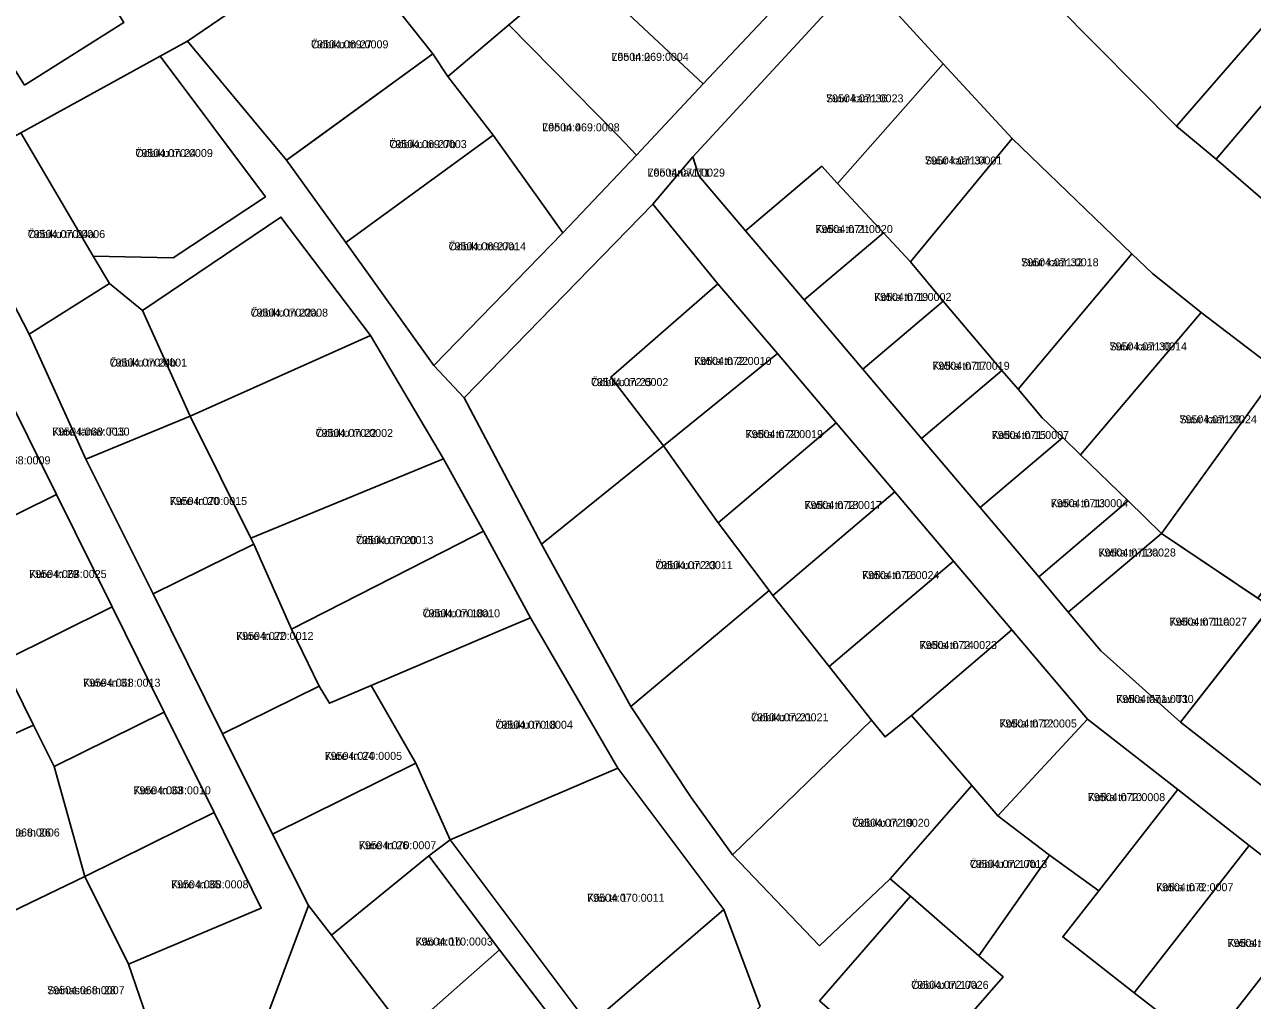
# Model space of a CAD drawing. Extents: x 643847 to 663718, y 6468443 to 6482775.
# Drawn here: x 658246.9 to 658477, y 6471809.8 to 6471992.7 of the extents above; entities that cross this region are included whole.
import ezdxf

# ---------------------------------------------------------------- set-up
doc = ezdxf.new("R2010")
doc.units = 0
for name, color, linetype in [('L_AADRESS', 7, 'Continuous'), ('PIIR', 7, 'Continuous'), ('TUNNUS', 7, 'Continuous')]:
    doc.layers.add(name, color=color, linetype=linetype)

msp = doc.modelspace()

# ---------------------------------------------------------------- linework, layer by layer
at = {"layer": 'PIIR'}
for points in [[(658486.97, 6471987.22), (658470.14, 6471967.41), (658462.76, 6471973.64), (658481.78, 6471995.53), (658502.37, 6472019.24), (658520.73, 6472040.77), (658544.18, 6472069.39), (658548.25, 6472074.35), (658574.77, 6472108.01), (658585.28, 6472121.63), (658597.38, 6472137.31), (658620.68, 6472168.8), (658629.38, 6472163.16), (658609.28, 6472136.89), (658597.33, 6472121.3), (658586.04, 6472105.83), (658580.96, 6472099.65), (658555.3, 6472067.81), (658551.14, 6472062.72), (658529, 6472036.46), (658513.76, 6472018.4), (658509.71, 6472013.53)], [(658379.22, 6472034.21), (658398.69, 6472007.8), (658374.03, 6471981.52), (658370.39, 6471984.94), (658350.57, 6472003.51), (658363.17, 6472017.02)], [(658440.06, 6471996.47), (658454.33, 6472012.08), (658459.63, 6472017.87), (658481.78, 6471995.53), (658462.76, 6471973.64)], [(658246.85, 6471981.3), (658232.47, 6472004.15), (658251.08, 6472015.88), (658265.46, 6471993.03)], [(658320.86, 6472000.73), (658340.33, 6472012.98), (658350.57, 6472003.51), (658337.64, 6471992.59), (658326.2, 6471982.92), (658323.4, 6471987.19), (658315.36, 6471997.27)], [(658277.4, 6471989.53), (658306.11, 6472009.17), (658315.36, 6471997.27), (658323.4, 6471987.19), (658299.95, 6471970.14), (658295.95, 6471967.23)], [(658403.66, 6472002.11), (658372.1, 6471967.86), (658364.62, 6471958.97), (658329.23, 6471922.68), (658323.57, 6471928.79), (658347.76, 6471953.61), (658361.56, 6471968.19), (658374.03, 6471981.52), (658398.69, 6472007.8)], [(658374.03, 6471981.52), (658361.56, 6471968.19), (658358.08, 6471971.8), (658337.64, 6471992.59), (658350.57, 6472003.51), (658370.39, 6471984.94)], [(658419.02, 6471985.3), (658399.22, 6471962.89), (658396.25, 6471966.11), (658381.99, 6471954.02), (658373.24, 6471964.3), (658372.1, 6471967.86), (658403.66, 6472002.11)], [(658347.76, 6471953.61), (658344.86, 6471957.67), (658334.69, 6471971.91), (658326.2, 6471982.92), (658337.64, 6471992.59), (658358.08, 6471971.8), (658361.56, 6471968.19)], [(658292.01, 6471960.35), (658274.73, 6471948.93), (658259.73, 6471949.27), (658246.18, 6471972.39), (658272.3, 6471986.72)], [(658323.4, 6471987.19), (658326.2, 6471982.92), (658334.69, 6471971.91), (658307.04, 6471951.8), (658295.95, 6471967.23)], [(658431.94, 6471971.31), (658412.91, 6471948.21), (658407.83, 6471953.64), (658399.22, 6471962.89), (658419.02, 6471985.3)], [(658470.14, 6471967.41), (658486.97, 6471987.22), (658503.61, 6471972.83), (658486.78, 6471953.07)], [(658259.73, 6471949.27), (658262.77, 6471944.1), (658247.71, 6471934.61), (658232.16, 6471964.7), (658246.18, 6471972.39)], [(658323.57, 6471928.79), (658307.04, 6471951.8), (658334.69, 6471971.91), (658344.86, 6471957.67), (658347.76, 6471953.61)], [(658454.35, 6471949.67), (658433.04, 6471924.32), (658429.98, 6471927.84), (658419.01, 6471940.82), (658412.91, 6471948.21), (658431.94, 6471971.31)], [(658381.99, 6471954.02), (658396.25, 6471966.11), (658399.22, 6471962.89), (658407.83, 6471953.64), (658392.98, 6471941.05)], [(658329.23, 6471922.68), (658364.62, 6471958.97), (658376.79, 6471944.06), (658356.73, 6471926.6), (658366.57, 6471913.68), (658343.75, 6471895.26)], [(658277.91, 6471919.28), (658268.94, 6471939.05), (658294.89, 6471956.56), (658311.71, 6471934.36)], [(658392.98, 6471941.05), (658407.83, 6471953.64), (658412.91, 6471948.21), (658419.01, 6471940.82), (658403.97, 6471928.08)], [(658458.25, 6471946), (658467.34, 6471938.7), (658444.74, 6471912.02), (658441.42, 6471915.25), (658437.57, 6471918.98), (658433.04, 6471924.32), (658454.35, 6471949.67)], [(658268.94, 6471939.05), (658277.91, 6471919.28), (658258.33, 6471911.21), (658247.71, 6471934.61), (658262.77, 6471944.1)], [(658387.97, 6471931.02), (658366.57, 6471913.68), (658356.73, 6471926.6), (658376.79, 6471944.06)], [(658403.97, 6471928.08), (658419.01, 6471940.82), (658429.98, 6471927.84), (658414.96, 6471915.11)], [(658467.34, 6471938.7), (658481.84, 6471927.64), (658459.94, 6471897.31), (658453.67, 6471903.38), (658444.74, 6471912.02)], [(658325.4, 6471911.26), (658289.25, 6471896.38), (658277.91, 6471919.28), (658311.71, 6471934.36)], [(658398.96, 6471918.05), (658376.84, 6471899.31), (658366.57, 6471913.68), (658387.97, 6471931.02)], [(658414.96, 6471915.11), (658429.98, 6471927.84), (658433.04, 6471924.32), (658437.57, 6471918.98), (658441.42, 6471915.25), (658425.95, 6471902.14)], [(658252.84, 6471904.59), (658232.22, 6471894.39), (658221.58, 6471915.89), (658226.96, 6471918.56), (658242.19, 6471926.09)], [(658499.39, 6471913.75), (658477.99, 6471885.14), (658459.94, 6471897.31), (658481.84, 6471927.64)], [(658258.33, 6471911.21), (658277.91, 6471919.28), (658289.25, 6471896.38), (658289.8, 6471895.3), (658270.95, 6471886)], [(658409.95, 6471905.08), (658387.07, 6471885.69), (658386.4, 6471886.58), (658376.84, 6471899.31), (658398.96, 6471918.05)], [(658436.94, 6471889.16), (658425.95, 6471902.14), (658441.42, 6471915.25), (658444.74, 6471912.02), (658453.67, 6471903.38)], [(658343.75, 6471895.26), (658366.57, 6471913.68), (658376.84, 6471899.31), (658386.4, 6471886.58), (658360.45, 6471864.86)], [(658332.85, 6471897.7), (658328.4, 6471895.42), (658296.91, 6471879.33), (658289.8, 6471895.3), (658289.25, 6471896.38), (658325.4, 6471911.26)], [(658420.94, 6471892.11), (658397.67, 6471872.39), (658387.07, 6471885.69), (658409.95, 6471905.08)], [(658263.26, 6471883.52), (658242.64, 6471873.32), (658235.36, 6471888.05), (658232.22, 6471894.39), (658252.84, 6471904.59)], [(658453.67, 6471903.38), (658459.94, 6471897.31), (658442.45, 6471882.56), (658436.94, 6471889.16)], [(658341.66, 6471881.49), (658337.07, 6471879.53), (658311.82, 6471868.79), (658304, 6471865.46), (658302.06, 6471868.7), (658296.91, 6471879.33), (658328.4, 6471895.42), (658332.85, 6471897.7)], [(658459.94, 6471897.31), (658478.02, 6471885.13), (658480.41, 6471883.57), (658463.45, 6471861.9), (658448.57, 6471875.27), (658442.45, 6471882.56)], [(658270.95, 6471886), (658289.8, 6471895.3), (658296.91, 6471879.33), (658302.06, 6471868.7), (658283.95, 6471859.74)], [(658431.89, 6471879.2), (658413.06, 6471863.18), (658408.11, 6471859.15), (658405.57, 6471862.28), (658397.67, 6471872.39), (658420.94, 6471892.11)], [(658207.37, 6471876.32), (658235.36, 6471888.05), (658242.64, 6471873.32), (658248.56, 6471861.38), (658218.77, 6471847.97)], [(658371.8, 6471847.82), (658360.45, 6471864.86), (658386.4, 6471886.58), (658387.07, 6471885.69), (658397.67, 6471872.39), (658405.57, 6471862.28), (658379.54, 6471837.07)], [(658273.02, 6471863.81), (658252.4, 6471853.61), (658248.56, 6471861.38), (658242.64, 6471873.32), (658263.26, 6471883.52)], [(658463.48, 6471861.9), (658480.38, 6471883.58), (658485.41, 6471880.31), (658487.09, 6471879.01), (658498.83, 6471869.87), (658481.63, 6471847.77)], [(658358.03, 6471853.3), (658326.65, 6471839.89), (658320.19, 6471854.22), (658311.82, 6471868.79), (658337.07, 6471879.53), (658341.66, 6471881.49)], [(658446.03, 6471862.48), (658429.27, 6471844.35), (658424.4, 6471850.05), (658413.06, 6471863.18), (658431.89, 6471879.2)], [(658283.95, 6471859.74), (658302.06, 6471868.7), (658304, 6471865.46), (658311.82, 6471868.79), (658320.19, 6471854.22), (658293.3, 6471840.92)], [(658282.37, 6471844.99), (658258.17, 6471833.02), (658252.4, 6471853.61), (658273.02, 6471863.81)], [(658218.77, 6471847.97), (658248.56, 6471861.38), (658252.4, 6471853.61), (658258.17, 6471833.02), (658230.36, 6471819.62)], [(658379.54, 6471837.07), (658405.57, 6471862.28), (658408.11, 6471859.15), (658413.06, 6471863.18), (658424.4, 6471850.05), (658409.1, 6471832.6), (658395.84, 6471820.03)], [(658462.95, 6471849.28), (658448.19, 6471830.35), (658438.92, 6471837), (658429.27, 6471844.35), (658446.03, 6471862.48)], [(658300.1, 6471827.59), (658293.3, 6471840.92), (658320.19, 6471854.22), (658326.65, 6471839.89), (658322.65, 6471836.89), (658304.36, 6471822.02)], [(658377.92, 6471826.8), (658352.67, 6471805.18), (658326.65, 6471839.89), (658358.03, 6471853.3)], [(658412.87, 6471829.31), (658409.1, 6471832.6), (658424.4, 6471850.05), (658429.27, 6471844.35), (658438.92, 6471837), (658425.69, 6471818.15)], [(658448.19, 6471830.35), (658462.95, 6471849.28), (658476.35, 6471838.83), (658454.82, 6471811.23), (658441.42, 6471821.68)], [(658291.23, 6471827.07), (658266.34, 6471816.6), (658258.17, 6471833.02), (658282.37, 6471844.99)], [(658377.92, 6471826.8), (658384.7, 6471808.64), (658370.37, 6471794.57), (658361.95, 6471786.11), (658359.27, 6471789.16), (658355, 6471785.23), (658330.45, 6471762.66), (658323.31, 6471756.93), (658307.14, 6471745.74), (658273.59, 6471720.09), (658264.99, 6471735.67), (658270.23, 6471731.61), (658281.89, 6471735.34), (658300.85, 6471749.01), (658316.72, 6471761.21), (658320.94, 6471764.7), (658337.26, 6471778.98), (658354.27, 6471795.15), (658335.85, 6471819.29), (658322.65, 6471836.89), (658326.65, 6471839.89), (658352.67, 6471805.18)], [(658489.75, 6471828.38), (658468.22, 6471800.78), (658467.51, 6471801.33), (658454.82, 6471811.23), (658476.35, 6471838.83)], [(658335.85, 6471819.29), (658318.33, 6471803.75), (658304.36, 6471822.02), (658322.65, 6471836.89)], [(658413.16, 6471794.6), (658430.22, 6471814.21), (658425.69, 6471818.15), (658438.92, 6471837), (658448.19, 6471830.35), (658441.42, 6471821.68), (658454.82, 6471811.23), (658467.51, 6471801.33), (658441.97, 6471768.76)], [(658230.36, 6471819.62), (658258.17, 6471833.02), (658266.34, 6471816.6), (658271.85, 6471800.57), (658242.75, 6471788.94)], [(658395.81, 6471809.7), (658412.87, 6471829.31), (658425.69, 6471818.15), (658430.22, 6471814.21), (658413.16, 6471794.6)], [(658320.94, 6471764.7), (658290.4, 6471801.72), (658300.1, 6471827.59), (658304.36, 6471822.02), (658318.33, 6471803.75), (658337.26, 6471778.98)], [(658503.15, 6471817.93), (658481.62, 6471790.33), (658468.22, 6471800.78), (658489.75, 6471828.38)], [(658337.26, 6471778.98), (658318.33, 6471803.75), (658335.85, 6471819.29), (658354.27, 6471795.15)]]:
    msp.add_lwpolyline(points, close=True, dxfattribs=at)
for points in [[(658481.84, 6471927.64), (658467.34, 6471938.7), (658458.25, 6471946), (658454.35, 6471949.67), (658431.94, 6471971.31), (658419.02, 6471985.3), (658403.66, 6472002.11), (658398.69, 6472007.8), (658418.28, 6472021.46), (658423.46, 6472015.52), (658440.06, 6471996.47), (658462.76, 6471973.64), (658470.14, 6471967.41), (658486.78, 6471953.07)], [(658306.11, 6472009.17), (658277.4, 6471989.53), (658272.3, 6471986.72), (658246.18, 6471972.39)], [(658246.85, 6471981.3), (658265.46, 6471993.03)], [(658384.7, 6471808.64), (658377.92, 6471826.8), (658358.03, 6471853.3), (658341.66, 6471881.49), (658332.85, 6471897.7), (658325.4, 6471911.26), (658311.71, 6471934.36), (658294.89, 6471956.56), (658268.94, 6471939.05), (658262.77, 6471944.1), (658259.73, 6471949.27), (658274.73, 6471948.93), (658292.01, 6471960.35), (658272.3, 6471986.72), (658277.4, 6471989.53), (658295.95, 6471967.23), (658307.04, 6471951.8), (658323.57, 6471928.79), (658329.23, 6471922.68), (658343.75, 6471895.26), (658360.45, 6471864.86), (658371.8, 6471847.82), (658379.54, 6471837.07), (658395.84, 6471820.03), (658409.1, 6471832.6), (658412.87, 6471829.31), (658395.81, 6471809.7)], [(658489.75, 6471828.38), (658476.35, 6471838.83), (658462.95, 6471849.28), (658446.03, 6471862.48), (658431.89, 6471879.2), (658420.94, 6471892.11), (658409.95, 6471905.08), (658398.96, 6471918.05), (658387.97, 6471931.02), (658376.79, 6471944.06), (658364.62, 6471958.97), (658372.1, 6471967.86), (658373.24, 6471964.3), (658381.99, 6471954.02), (658392.98, 6471941.05), (658403.97, 6471928.08), (658414.96, 6471915.11), (658425.95, 6471902.14), (658436.94, 6471889.16), (658442.45, 6471882.56), (658448.57, 6471875.27), (658463.45, 6471861.9), (658481.63, 6471847.77)], [(658232.16, 6471964.7), (658247.71, 6471934.61), (658258.33, 6471911.21), (658270.95, 6471886), (658283.95, 6471859.74), (658293.3, 6471840.92), (658300.1, 6471827.59), (658290.4, 6471801.72), (658320.94, 6471764.7), (658316.72, 6471761.21), (658296.98, 6471785.11), (658291.89, 6471780.91), (658276.11, 6471802.62), (658271.85, 6471800.57), (658266.34, 6471816.6), (658291.23, 6471827.07), (658282.37, 6471844.99), (658273.02, 6471863.81), (658263.26, 6471883.52), (658252.84, 6471904.59), (658242.19, 6471926.09)]]:
    msp.add_lwpolyline(points, dxfattribs=at)

# ---------------------------------------------------------------- texts
at = {"layer": 'L_AADRESS'}
for s, p in [('Ööbiku tn 27', (658300.55, 6471988.2)), ('Lõo tn 2', (658356.84, 6471985.85)), ('Suur kaar 36', (658397.07, 6471978.07)), ('Lõo tn 4', (658343.88, 6471972.64)), ('Ööbiku tn 24', (658267.64, 6471967.82)), ('Ööbiku tn 27b', (658315.22, 6471969.5)), ('Suur kaar 34', (658415.58, 6471966.43)), ('Lõo tänav T1', (658363.61, 6471964.16)), ('Ööbiku tn 24a', (658247.46, 6471952.64)), ('Kotka tn 21', (658395.06, 6471953.58)), ('Ööbiku tn 27a', (658326.33, 6471950.35)), ('Suur kaar 32', (658433.63, 6471947.35)), ('Kotka tn 19', (658406.06, 6471940.86)), ('Ööbiku tn 22a', (658289.23, 6471937.92)), ('Suur kaar 30', (658450.19, 6471931.59)), ('Ööbiku tn 24b', (658262.81, 6471928.56)), ('Kotka tn 22', (658372.33, 6471928.87)), ('Kotka tn 17', (658416.97, 6471927.96)), ('Ööbiku tn 25', (658353.01, 6471924.9)), ('Suur kaar 28', (658463.29, 6471917.93)), ('Kure tänav T15', (658252.04, 6471915.63)), ('Ööbiku tn 22', (658301.41, 6471915.37)), ('Kotka tn 20', (658381.98, 6471915.16)), ('Kotka tn 15', (658428.09, 6471914.99)), ('Kure tn 20', (658274.06, 6471902.62)), ('Kotka tn 18', (658393.01, 6471901.87)), ('Kotka tn 13', (658439.16, 6471902.21)), ('Ööbiku tn 20', (658308.98, 6471895.29)), ('Kotka tn 13a', (658448.11, 6471892.97)), ('Ööbiku tn 23', (658365.07, 6471890.6)), ('Kure tn 29', (658247.74, 6471888.95)), ('Kotka tn 16', (658403.81, 6471888.74)), ('Ööbiku tn 18a', (658321.46, 6471881.58)), ('Kotka tn 11a', (658461.43, 6471880.01)), ('Kure tn 22', (658286.51, 6471877.34)), ('Kotka tn 14', (658414.59, 6471875.63)), ('Kure tn 31', (658257.83, 6471868.57)), ('Kotka tänav T1', (658451.44, 6471865.52)), ('Ööbiku tn 21', (658383.01, 6471862.09)), ('Ööbiku tn 18', (658335.11, 6471860.69)), ('Kotka tn 12', (658429.55, 6471860.93)), ('Kure tn 24', (658303.1, 6471854.86)), ('Kure tn 33', (658267.26, 6471848.41)), ('Kotka tn 10', (658446.11, 6471847.13)), ('Ööbiku tn 19', (658401.97, 6471842.32)), ('Soinaste tn 26', (658238.95, 6471840.5)), ('Kure tn 26', (658309.51, 6471838.12)), ('Ööbiku tn 17b', (658424.01, 6471834.61)), ('Kure tn 35', (658274.33, 6471830.79)), ('Kotka tn 8', (658458.89, 6471830.25)), ('Käo tn 1', (658352.29, 6471828.27)), ('Käo tn 1b', (658320.11, 6471820.07)), ('Kotka tn 6', (658472.29, 6471819.8)), ('Ööbiku tn 17a', (658413.02, 6471811.95)), ('Soinaste tn 28', (658251.11, 6471810.95))]:
    msp.add_text(s, height=1.5, dxfattribs=at).set_placement(p)
at = {"layer": 'TUNNUS'}
for s, p in [('79504:069:0009', (658300.55, 6471988.2)), ('79504:069:0004', (658356.84, 6471985.85)), ('79504:071:0023', (658397.07, 6471978.07)), ('79504:069:0008', (658343.88, 6471972.64)), ('79504:070:0009', (658267.64, 6471967.82)), ('79504:069:0003', (658315.22, 6471969.5)), ('79504:071:0001', (658415.58, 6471966.43)), ('79504:071:0029', (658363.61, 6471964.16)), ('79504:070:0006', (658247.46, 6471952.64)), ('79504:071:0020', (658395.06, 6471953.58)), ('79504:069:0014', (658326.33, 6471950.35)), ('79504:071:0018', (658433.63, 6471947.35)), ('79504:071:0002', (658406.06, 6471940.86)), ('79504:070:0008', (658289.23, 6471937.92)), ('79504:071:0014', (658450.19, 6471931.59)), ('79504:070:0001', (658262.81, 6471928.56)), ('79504:072:0010', (658372.33, 6471928.87)), ('79504:071:0019', (658416.97, 6471927.96)), ('79504:072:0002', (658353.01, 6471924.9)), ('79504:071:0024', (658463.29, 6471917.93)), ('79504:068:0030', (658252.04, 6471915.63)), ('79504:070:0002', (658301.41, 6471915.37)), ('79504:072:0019', (658381.98, 6471915.16)), ('79504:071:0007', (658428.09, 6471914.99)), ('79504:068:0009', (658237.21, 6471910.24)), ('79504:070:0015', (658274.06, 6471902.62)), ('79504:072:0017', (658393.01, 6471901.87)), ('79504:071:0004', (658439.16, 6471902.21)), ('79504:070:0013', (658308.98, 6471895.29)), ('79504:071:0028', (658448.11, 6471892.97)), ('79504:072:0011', (658365.07, 6471890.6)), ('79504:068:0025', (658247.74, 6471888.95)), ('79504:072:0024', (658403.81, 6471888.74)), ('79504:070:0010', (658321.46, 6471881.58)), ('79504:071:0027', (658461.43, 6471880.01)), ('79504:070:0012', (658286.51, 6471877.34)), ('79504:072:0023', (658414.59, 6471875.63)), ('79504:068:0013', (658257.83, 6471868.57)), ('79504:071:0030', (658451.44, 6471865.52)), ('79504:072:0021', (658383.01, 6471862.09)), ('79504:070:0004', (658335.11, 6471860.69)), ('79504:072:0005', (658429.55, 6471860.93)), ('79504:070:0005', (658303.1, 6471854.86)), ('79504:068:0010', (658267.26, 6471848.41)), ('79504:072:0008', (658446.11, 6471847.13)), ('79504:072:0020', (658401.97, 6471842.32)), ('79504:068:0006', (658238.95, 6471840.5)), ('79504:070:0007', (658309.51, 6471838.12)), ('79504:072:0013', (658424.01, 6471834.61)), ('79504:068:0008', (658274.33, 6471830.79)), ('79504:072:0007', (658458.89, 6471830.25)), ('79504:070:0011', (658352.29, 6471828.27)), ('79504:070:0003', (658320.11, 6471820.07)), ('79504:072:0014', (658472.29, 6471819.8)), ('79504:072:0026', (658413.02, 6471811.95)), ('79504:068:0007', (658251.11, 6471810.95))]:
    msp.add_text(s, height=1.5, dxfattribs=at).set_placement(p)

doc.saveas('drawing.dxf')
